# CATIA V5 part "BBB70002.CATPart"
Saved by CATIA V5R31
Part number: BBB70002
Revision: 1
Nomenclature: BRKT_B
Source: Unknown
Property "部品番号(A社)": "BBB70002"
Property "部品名称(A社)": "BRKT_B"
Property "Version(A社)": "1"
Property "材質": "JSH270C"
Property "板厚": "2.3"
Bounding box of the stored display mesh (mm): x -708.278 to -629.086, y -102.954 to -70.935, z -29.598 to 29.012
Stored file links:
  \\cad-nas02\CATIA1212\BODY_DEPARTMENT8\JAMA\変換データ\STEP3_最終_20240115\01_いすゞ板金\new_ファイル名修正後\CATIA_V5_20240122\BBB70002.CATPart
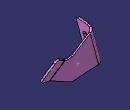
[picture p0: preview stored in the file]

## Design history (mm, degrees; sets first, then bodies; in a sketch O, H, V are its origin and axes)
Set1
  DatumPoint1
  DatumPoint2
Body1 "MANIFOLD_SOLID_BREP #329" (main body)
  Solid1: solid without history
